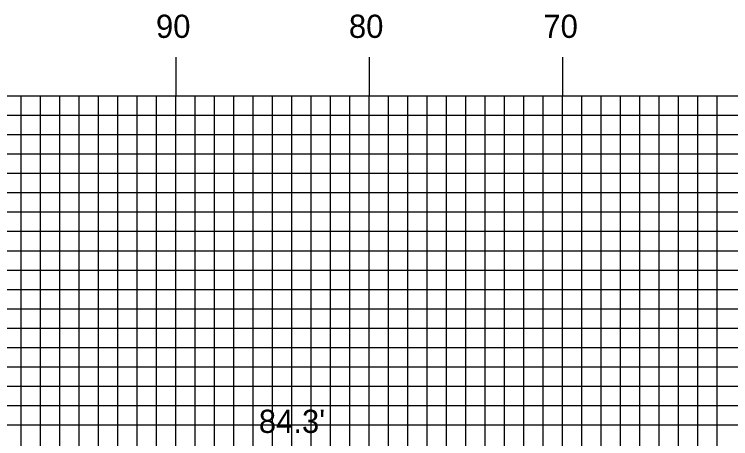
# Model space of a CAD drawing. Extents: x 1781467 to 1781810, y 442591 to 442811.
# Drawn here: x 1781534.06 to 1781571.1, y 442680.95 to 442702.88 of the extents above; entities that cross this region are included whole.
import ezdxf

# ---------------------------------------------------------------- set-up
doc = ezdxf.new("R2010")
doc.units = 0
for name, color, linetype in [('D_Text_Standard', 7, 'Continuous'), ('H_V ANNOTATION', 7, 'Continuous'), ('MAJOR', 7, 'Continuous'), ('MINOR', 7, 'Continuous')]:
    doc.layers.add(name, color=color, linetype=linetype)

msp = doc.modelspace()

# ---------------------------------------------------------------- linework, layer by layer
at = {"layer": 'MAJOR'}
for p, q in [((1781542.408, 442700.669), (1781542.408, 442698.665)), ((1781552.408, 442700.669), (1781552.408, 442698.665)), ((1781562.408, 442700.669), (1781562.408, 442698.665)), ((1781492.408, 442698.665), (1781772.408, 442698.665)), ((1781492.408, 442698.665), (1781772.408, 442698.665)), ((1781542.408, 442663.665), (1781542.408, 442698.665)), ((1781552.408, 442663.665), (1781552.408, 442698.665)), ((1781562.408, 442663.665), (1781562.408, 442698.665)), ((1781492.408, 442693.665), (1781772.408, 442693.665)), ((1781492.408, 442688.665), (1781772.408, 442688.665)), ((1781492.408, 442683.665), (1781772.408, 442683.665))]:
    msp.add_line(p, q, dxfattribs=at)
at = {"layer": 'MINOR'}
for p, q in [((1781534.408, 442663.665), (1781534.408, 442698.665)), ((1781535.408, 442663.665), (1781535.408, 442698.665)), ((1781536.408, 442663.665), (1781536.408, 442698.665)), ((1781537.408, 442663.665), (1781537.408, 442698.665)), ((1781538.408, 442663.665), (1781538.408, 442698.665)), ((1781539.408, 442663.665), (1781539.408, 442698.665)), ((1781540.408, 442663.665), (1781540.408, 442698.665)), ((1781541.408, 442663.665), (1781541.408, 442698.665)), ((1781543.408, 442663.665), (1781543.408, 442698.665)), ((1781544.408, 442663.665), (1781544.408, 442698.665)), ((1781545.408, 442663.665), (1781545.408, 442698.665)), ((1781546.408, 442663.665), (1781546.408, 442698.665)), ((1781547.408, 442663.665), (1781547.408, 442698.665)), ((1781548.408, 442663.665), (1781548.408, 442698.665)), ((1781549.408, 442663.665), (1781549.408, 442698.665)), ((1781550.408, 442663.665), (1781550.408, 442698.665)), ((1781551.408, 442663.665), (1781551.408, 442698.665)), ((1781553.408, 442663.665), (1781553.408, 442698.665)), ((1781554.408, 442663.665), (1781554.408, 442698.665)), ((1781555.408, 442663.665), (1781555.408, 442698.665)), ((1781556.408, 442663.665), (1781556.408, 442698.665)), ((1781557.408, 442663.665), (1781557.408, 442698.665)), ((1781558.408, 442663.665), (1781558.408, 442698.665)), ((1781559.408, 442663.665), (1781559.408, 442698.665)), ((1781560.408, 442663.665), (1781560.408, 442698.665)), ((1781561.408, 442663.665), (1781561.408, 442698.665)), ((1781563.408, 442663.665), (1781563.408, 442698.665)), ((1781564.408, 442663.665), (1781564.408, 442698.665)), ((1781565.408, 442663.665), (1781565.408, 442698.665)), ((1781566.408, 442663.665), (1781566.408, 442698.665)), ((1781567.408, 442663.665), (1781567.408, 442698.665)), ((1781568.408, 442663.665), (1781568.408, 442698.665)), ((1781569.408, 442663.665), (1781569.408, 442698.665)), ((1781570.408, 442663.665), (1781570.408, 442698.665)), ((1781492.408, 442697.665), (1781772.408, 442697.665)), ((1781492.408, 442696.665), (1781772.408, 442696.665)), ((1781492.408, 442695.665), (1781772.408, 442695.665)), ((1781492.408, 442694.665), (1781772.408, 442694.665)), ((1781492.408, 442692.665), (1781772.408, 442692.665)), ((1781492.408, 442691.665), (1781772.408, 442691.665)), ((1781492.408, 442690.665), (1781772.408, 442690.665)), ((1781492.408, 442689.665), (1781772.408, 442689.665)), ((1781492.408, 442687.665), (1781772.408, 442687.665)), ((1781492.408, 442686.665), (1781772.408, 442686.665)), ((1781492.408, 442685.665), (1781772.408, 442685.665)), ((1781492.408, 442684.665), (1781772.408, 442684.665)), ((1781492.408, 442682.665), (1781772.408, 442682.665)), ((1781492.408, 442681.665), (1781772.408, 442681.665))]:
    msp.add_line(p, q, dxfattribs=at)

# ---------------------------------------------------------------- texts
at = {"layer": 'D_Text_Standard'}
msp.add_text("84.3'", height=1.2, dxfattribs=at).set_placement((1781546.7, 442681.243))
at = {"layer": 'H_V ANNOTATION'}
for s, p in [('90', (1781541.38, 442701.665)), ('80', (1781551.359, 442701.665)), ('70', (1781561.412, 442701.665))]:
    msp.add_text(s, height=1.2, dxfattribs=at).set_placement(p)

doc.saveas('drawing.dxf')
